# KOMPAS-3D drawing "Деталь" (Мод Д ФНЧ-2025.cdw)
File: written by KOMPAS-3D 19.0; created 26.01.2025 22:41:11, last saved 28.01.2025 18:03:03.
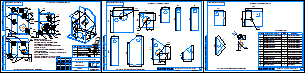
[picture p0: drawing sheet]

Sheets 1-3: A3, landscape

Document properties: Автор: Степан; Полное имя файла: C:\Users\WELDER_72\OneDrive\Desktop\ггавп\КОМПАС 3Д\Мод Д ФНЧ-2025.cdw; Масса: 1.19425; Форматы листов документа: 3xA3

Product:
- Part/product: Деталь
    Материал: АМг3 ГОСТ 4784-2019 (density 2680 kg/m3)
    Масса: 1.19425
  - Body: Тело 19
      Масса: 0.0938474
  - Body: Тело 16
      Масса: 0.0752544
  - Body: Тело 15
      Масса: 0.0750268
  - Body: Тело 14
      Масса: 0.06633
  - Body: Тело 13
      Масса: 0.101706
  - Body: Тело 9
      Масса: 0.0394031
  - Body: Тело 8
      Масса: 0.30578
  - Body: Тело 7
      Масса: 0.30578
  - Body: Тело 4
      Масса: 0.046431
  - Body: Тело 3
      Масса: 0.030954
  - Body: Тело 2
      Масса: 0.046431
  - Body: Тело 1
      Масса: 0.212188
  - Body: Тело 17
      Масса: 0.043416
  - Body: Тело 18
      Масса: 0.057486

Title block, sheet 1: Наименование: Модуль Д / ФНЧ-2025; designation: Процесс сварки 141 (РАД); Материал: АМг-3; Масса: 1,19; sheet number: 1; Количество листов документа: 3; organisation: Чемпионат ПМ / "Профессионалы"; Форматы листов документа: A3; stored path: C:\Users\Степан\Desktop\Модули на РЧ\Модуль Д Степанов.cdw; Разработал: Степанов С.С.; Проверил: Калашников В.А.; Утвердил: Дюкова С. В.
Title block, sheet 2: sheet number: 2
Title block, sheet 3: sheet number: 3

Views: Спереди 1, Спереди, Проекционный вид 2, Проекционный вид 3
Referenced files in C:\Users\Степан\Desktop\Модули на РЧ\: Модуль Д Степанов.m3d
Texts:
  Технические условия:
  1. Сварка на спуск запрещена;
  2. Наличие зазоров и прихватки внутри
  конструкции не допускаются;
  3. Все стыковые и угловые швы выполняются
  с полным проваром;
  4. Сварка производится относительно пластины "1"
  в нижнем положении;
  5. Все швы выполняются в один проход с применением
  присадочной проволоки;
  6. Изделие сдается на проверку без очистки;
  7. Длина прихваток не более 10 мм.
  Все расмеры на чертеже указаны в миллиметрах
  № шва
  Стандарт и обозначение
  Кол-во
  ГОСТ 14806-80-Т1- 3 +2
  ГОСТ 14806-80-У4- 3 +3
  ГОСТ 14806-80-С2
  ГОСТ 23518-79-У1- 3 +6
  № дет.
  Наименование, размеры
  шт.
  Пластина 3х180х168 с с отв.  70 мм
  Прямоугольная форма
  Пластина 3х115х110с отв.  65 мм
  Пластина 3х110х65
  Пластина 3х180х30
  Пластина 3х180х52
  Пластина 3х230х55
  Пластина 3х230х100
  Сложная форма, см. чертеж
  Пластина 3х180х100 с отв.  60 мм
  Пластина 3х110х70
  Пластина 3х140х55
  Пластина 3х110х75
  Пластина 3х140х122 с отв.  30 мм
  Труба  42х3 - 30
  См. чертеж
  Сборочно-сварочный чертеж
  Деталировочный чертеж
  Пользовательская 4
  Пользовательская
Dimensions and other numbers on the sheet: 5; 6; 7; 8; 13; 1; 9; 2; 10; 3; 4; 22 2; 40 2; 11; 12; 29 2; 25 2; 168; 180; 80; 50; 70; 110; 115; 57,5; 55; 65; 30; 52; 230; 40; 185; 100; 60; 75; 122; 140; 61; 42; 89; 1:2,2; 1,19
